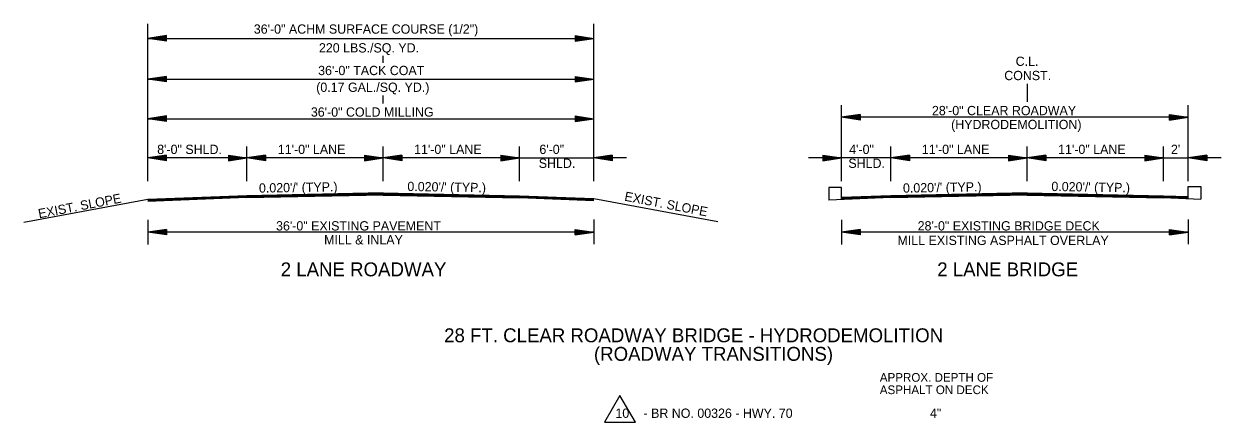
# Model space of a CAD drawing. Extents: x 549600 to 1930787, y -1955432 to 596640.
# Drawn here: x 551046 to 552013, y -1948810 to -1948488 of the extents above; entities that cross this region are included whole.
import ezdxf

# ---------------------------------------------------------------- set-up
doc = ezdxf.new("R2010")
doc.units = 0
for name, color, linetype in [('R_Border', 7, 'Continuous'), ('R_Border Notes', 7, 'Continuous'), ('S_AREA_CALC', 7, 'Continuous')]:
    doc.layers.add(name, color=color, linetype=linetype)

msp = doc.modelspace()

# ---------------------------------------------------------------- linework, layer by layer
at = {"layer": 'R_Border'}
for p, q in [((551856.56, -1948536.2), (551856.56, -1948550.7)), ((551696.39, -1948619.94), (551696.39, -1948630.06)), ((551706.56, -1948619.94), (551696.39, -1948619.94)), ((551706.56, -1948629.35), (551706.56, -1948619.94)), ((551986.56, -1948628.55), (551986.56, -1948619.14)), ((551986.56, -1948619.14), (551996.73, -1948619.14)), ((551996.73, -1948619.14), (551996.73, -1948629.26)), ((551515.35, -1948809.5), (551540.15, -1948809.5))]:
    msp.add_line(p, q, dxfattribs=at)
msp.add_lwpolyline([(551540.15, -1948809.5), (551527.75, -1948788.03), (551515.35, -1948809.5)], dxfattribs=at)
at = {"layer": 'S_AREA_CALC'}
for p, q in [((551146.56, -1948614.8), (551146.56, -1948487.77)), ((551506.56, -1948614.8), (551506.56, -1948487.77)), ((551161.56, -1948497.19), (551146.56, -1948499.44)), ((551146.56, -1948499.44), (551506.56, -1948499.44)), ((551161.56, -1948501.69), (551146.56, -1948499.44)), ((551161.56, -1948497.56), (551149.06, -1948499.44)), ((551161.56, -1948501.31), (551149.06, -1948499.44)), ((551161.56, -1948497.95), (551151.64, -1948499.44)), ((551161.56, -1948500.93), (551151.64, -1948499.44)), ((551161.56, -1948498.32), (551154.14, -1948499.44)), ((551161.56, -1948500.56), (551154.14, -1948499.44)), ((551161.56, -1948498.7), (551156.68, -1948499.44)), ((551161.56, -1948500.17), (551156.68, -1948499.44)), ((551161.56, -1948499.09), (551159.19, -1948499.44)), ((551161.56, -1948499.79), (551159.19, -1948499.44)), ((551161.56, -1948501.69), (551161.56, -1948497.19)), ((551491.56, -1948497.19), (551506.56, -1948499.44)), ((551491.56, -1948497.19), (551491.56, -1948501.69)), ((551491.56, -1948497.56), (551504.05, -1948499.44)), ((551491.56, -1948497.95), (551501.47, -1948499.44)), ((551491.56, -1948498.32), (551498.98, -1948499.44)), ((551491.56, -1948498.71), (551496.43, -1948499.44)), ((551491.56, -1948499.09), (551493.93, -1948499.44)), ((551491.56, -1948501.69), (551506.56, -1948499.44)), ((551491.56, -1948500.17), (551496.43, -1948499.44)), ((551491.56, -1948500.93), (551501.47, -1948499.44)), ((551491.56, -1948501.31), (551504.05, -1948499.44)), ((551491.56, -1948500.56), (551498.98, -1948499.44)), ((551491.56, -1948499.79), (551493.93, -1948499.44)), ((551336.56, -1948519.18), (551336.56, -1948513.65)), ((551161.56, -1948530.15), (551146.56, -1948532.4)), ((551146.56, -1948532.4), (551506.56, -1948532.4)), ((551161.56, -1948534.65), (551146.56, -1948532.4)), ((551161.56, -1948530.53), (551149.06, -1948532.4)), ((551161.56, -1948534.28), (551149.06, -1948532.4)), ((551161.56, -1948530.91), (551151.64, -1948532.4)), ((551161.56, -1948533.9), (551151.64, -1948532.4)), ((551161.56, -1948531.29), (551154.14, -1948532.4)), ((551161.56, -1948533.52), (551154.14, -1948532.4)), ((551161.56, -1948531.67), (551156.68, -1948532.4)), ((551161.56, -1948533.13), (551156.68, -1948532.4)), ((551161.56, -1948532.05), (551159.19, -1948532.4)), ((551161.56, -1948532.76), (551159.19, -1948532.4)), ((551161.56, -1948534.65), (551161.56, -1948530.15)), ((551491.56, -1948530.15), (551506.56, -1948532.4)), ((551491.56, -1948530.15), (551491.56, -1948534.65)), ((551491.56, -1948530.53), (551504.05, -1948532.4)), ((551491.56, -1948530.91), (551501.47, -1948532.4)), ((551491.56, -1948531.29), (551498.98, -1948532.4)), ((551491.56, -1948531.68), (551496.43, -1948532.4)), ((551491.56, -1948532.05), (551493.93, -1948532.4)), ((551491.56, -1948534.65), (551506.56, -1948532.4)), ((551491.56, -1948533.14), (551496.43, -1948532.4)), ((551491.56, -1948533.9), (551501.47, -1948532.4)), ((551491.56, -1948534.28), (551504.05, -1948532.4)), ((551491.56, -1948533.52), (551498.98, -1948532.4)), ((551491.56, -1948532.76), (551493.93, -1948532.4)), ((551336.56, -1948552.15), (551336.56, -1948545.73)), ((551706.56, -1948614.8), (551706.56, -1948553.31)), ((551986.56, -1948614.8), (551986.56, -1948553.31)), ((551161.56, -1948562.13), (551146.56, -1948564.38)), ((551146.56, -1948564.38), (551506.56, -1948564.38)), ((551161.56, -1948566.63), (551146.56, -1948564.38)), ((551161.56, -1948562.5), (551149.06, -1948564.38)), ((551161.56, -1948566.25), (551149.06, -1948564.38)), ((551161.56, -1948562.89), (551151.64, -1948564.38)), ((551161.56, -1948565.87), (551151.64, -1948564.38)), ((551161.56, -1948563.26), (551154.14, -1948564.38)), ((551161.56, -1948565.5), (551154.14, -1948564.38)), ((551161.56, -1948563.64), (551156.68, -1948564.38)), ((551161.56, -1948565.11), (551156.68, -1948564.38)), ((551161.56, -1948564.03), (551159.19, -1948564.38)), ((551161.56, -1948564.73), (551159.19, -1948564.38)), ((551161.56, -1948566.63), (551161.56, -1948562.13)), ((551491.56, -1948562.13), (551506.56, -1948564.38)), ((551491.56, -1948562.13), (551491.56, -1948566.63)), ((551491.56, -1948562.5), (551504.05, -1948564.38)), ((551491.56, -1948562.89), (551501.47, -1948564.38)), ((551491.56, -1948563.26), (551498.98, -1948564.38)), ((551491.56, -1948563.65), (551496.43, -1948564.38)), ((551491.56, -1948564.03), (551493.93, -1948564.38)), ((551491.56, -1948566.63), (551506.56, -1948564.38)), ((551491.56, -1948565.11), (551496.43, -1948564.38)), ((551491.56, -1948565.87), (551501.47, -1948564.38)), ((551491.56, -1948566.25), (551504.05, -1948564.38)), ((551491.56, -1948565.5), (551498.98, -1948564.38)), ((551491.56, -1948564.73), (551493.93, -1948564.38)), ((551721.56, -1948560.95), (551706.56, -1948563.2)), ((551986.56, -1948563.2), (551706.56, -1948563.2)), ((551721.56, -1948565.45), (551706.56, -1948563.2)), ((551721.56, -1948561.33), (551709.06, -1948563.2)), ((551721.56, -1948565.08), (551709.06, -1948563.2)), ((551721.56, -1948561.71), (551711.64, -1948563.2)), ((551721.56, -1948564.7), (551711.64, -1948563.2)), ((551721.56, -1948562.09), (551714.14, -1948563.2)), ((551721.56, -1948564.32), (551714.14, -1948563.2)), ((551721.56, -1948562.48), (551716.68, -1948563.2)), ((551721.56, -1948563.94), (551716.68, -1948563.2)), ((551721.56, -1948562.85), (551719.19, -1948563.2)), ((551721.56, -1948563.56), (551719.19, -1948563.2)), ((551721.56, -1948560.95), (551721.56, -1948565.45)), ((551971.56, -1948560.95), (551986.56, -1948563.2)), ((551971.56, -1948565.45), (551971.56, -1948560.95)), ((551971.56, -1948561.33), (551984.05, -1948563.2)), ((551971.56, -1948561.71), (551981.47, -1948563.2)), ((551971.56, -1948562.09), (551978.98, -1948563.2)), ((551971.56, -1948562.47), (551976.43, -1948563.2)), ((551971.56, -1948562.85), (551973.93, -1948563.2)), ((551971.56, -1948565.45), (551986.56, -1948563.2)), ((551971.56, -1948563.93), (551976.43, -1948563.2)), ((551971.56, -1948564.7), (551981.47, -1948563.2)), ((551971.56, -1948565.08), (551984.05, -1948563.2)), ((551971.56, -1948564.32), (551978.98, -1948563.2)), ((551971.56, -1948563.56), (551973.93, -1948563.2)), ((551226.56, -1948614.8), (551226.56, -1948586.85)), ((551336.56, -1948614.8), (551336.56, -1948586.85)), ((551446.56, -1948614.8), (551446.56, -1948586.85)), ((551746.56, -1948614.8), (551746.56, -1948586.85)), ((551856.56, -1948614.8), (551856.56, -1948586.85)), ((551966.56, -1948614.8), (551966.56, -1948586.85)), ((551161.56, -1948593.79), (551146.56, -1948596.04)), ((551226.56, -1948596.04), (551146.56, -1948596.04)), ((551161.56, -1948598.29), (551146.56, -1948596.04)), ((551161.56, -1948594.16), (551149.06, -1948596.04)), ((551161.56, -1948597.91), (551149.06, -1948596.04)), ((551161.56, -1948594.55), (551151.64, -1948596.04)), ((551161.56, -1948597.53), (551151.64, -1948596.04)), ((551161.56, -1948594.92), (551154.14, -1948596.04)), ((551161.56, -1948597.16), (551154.14, -1948596.04)), ((551161.56, -1948595.3), (551156.68, -1948596.04)), ((551161.56, -1948596.77), (551156.68, -1948596.04)), ((551161.56, -1948595.69), (551159.19, -1948596.04)), ((551161.56, -1948596.39), (551159.19, -1948596.04)), ((551161.56, -1948598.29), (551161.56, -1948593.79)), ((551211.56, -1948593.79), (551226.56, -1948596.04)), ((551211.56, -1948593.79), (551211.56, -1948598.29)), ((551211.56, -1948594.16), (551224.05, -1948596.04)), ((551211.56, -1948594.55), (551221.47, -1948596.04)), ((551211.56, -1948594.92), (551218.98, -1948596.04)), ((551211.56, -1948595.31), (551216.43, -1948596.04)), ((551211.56, -1948595.69), (551213.93, -1948596.04)), ((551211.56, -1948598.29), (551226.56, -1948596.04)), ((551211.56, -1948596.77), (551216.43, -1948596.04)), ((551211.56, -1948597.53), (551221.47, -1948596.04)), ((551211.56, -1948597.91), (551224.05, -1948596.04)), ((551211.56, -1948597.16), (551218.98, -1948596.04)), ((551211.56, -1948596.39), (551213.93, -1948596.04)), ((551241.56, -1948593.79), (551226.56, -1948596.04)), ((551336.56, -1948596.04), (551226.56, -1948596.04)), ((551241.56, -1948598.29), (551226.56, -1948596.04)), ((551241.56, -1948594.16), (551229.06, -1948596.04)), ((551241.56, -1948597.91), (551229.06, -1948596.04)), ((551241.56, -1948594.55), (551231.64, -1948596.04)), ((551241.56, -1948597.53), (551231.64, -1948596.04)), ((551241.56, -1948594.92), (551234.14, -1948596.04)), ((551241.56, -1948597.16), (551234.14, -1948596.04)), ((551241.56, -1948595.31), (551236.68, -1948596.04)), ((551241.56, -1948596.77), (551236.68, -1948596.04)), ((551241.56, -1948595.69), (551239.19, -1948596.04)), ((551241.56, -1948596.39), (551239.19, -1948596.04)), ((551241.56, -1948593.79), (551241.56, -1948598.29)), ((551321.56, -1948593.79), (551336.56, -1948596.04)), ((551321.56, -1948593.79), (551321.56, -1948598.29)), ((551321.56, -1948594.16), (551334.05, -1948596.04)), ((551321.56, -1948594.55), (551331.47, -1948596.04)), ((551321.56, -1948594.92), (551328.98, -1948596.04)), ((551321.56, -1948595.31), (551326.43, -1948596.04)), ((551321.56, -1948595.69), (551323.93, -1948596.04)), ((551321.56, -1948598.29), (551336.56, -1948596.04)), ((551321.56, -1948596.77), (551326.43, -1948596.04)), ((551321.56, -1948597.53), (551331.47, -1948596.04)), ((551321.56, -1948597.91), (551334.05, -1948596.04)), ((551321.56, -1948597.16), (551328.98, -1948596.04)), ((551321.56, -1948596.39), (551323.93, -1948596.04)), ((551351.56, -1948593.79), (551336.56, -1948596.04)), ((551446.56, -1948596.04), (551336.56, -1948596.04)), ((551351.56, -1948598.29), (551336.56, -1948596.04)), ((551351.56, -1948594.16), (551339.06, -1948596.04)), ((551351.56, -1948597.91), (551339.06, -1948596.04)), ((551351.56, -1948594.55), (551341.64, -1948596.04)), ((551351.56, -1948597.53), (551341.64, -1948596.04)), ((551351.56, -1948594.92), (551344.14, -1948596.04)), ((551351.56, -1948597.16), (551344.14, -1948596.04)), ((551351.56, -1948595.31), (551346.68, -1948596.04)), ((551351.56, -1948596.77), (551346.68, -1948596.04)), ((551351.56, -1948595.69), (551349.19, -1948596.04)), ((551351.56, -1948596.39), (551349.19, -1948596.04)), ((551351.56, -1948593.79), (551351.56, -1948598.29)), ((551431.56, -1948593.79), (551446.56, -1948596.04)), ((551431.56, -1948593.79), (551431.56, -1948598.29)), ((551431.56, -1948594.16), (551444.05, -1948596.04)), ((551431.56, -1948594.55), (551441.47, -1948596.04)), ((551431.56, -1948594.92), (551438.98, -1948596.04)), ((551431.56, -1948595.31), (551436.43, -1948596.04)), ((551431.56, -1948595.69), (551433.93, -1948596.04)), ((551431.56, -1948598.29), (551446.56, -1948596.04)), ((551431.56, -1948596.77), (551436.43, -1948596.04)), ((551431.56, -1948597.53), (551441.47, -1948596.04)), ((551431.56, -1948597.91), (551444.05, -1948596.04)), ((551431.56, -1948597.16), (551438.98, -1948596.04)), ((551431.56, -1948596.39), (551433.93, -1948596.04)), ((551446.56, -1948596.04), (551506.56, -1948596.04)), ((551521.56, -1948593.79), (551506.56, -1948596.04)), ((551521.56, -1948598.29), (551506.56, -1948596.04)), ((551533.08, -1948596.04), (551506.56, -1948596.04)), ((551521.56, -1948594.16), (551509.06, -1948596.04)), ((551521.56, -1948597.91), (551509.06, -1948596.04)), ((551521.56, -1948594.55), (551511.64, -1948596.04)), ((551521.56, -1948597.53), (551511.64, -1948596.04)), ((551521.56, -1948594.92), (551514.14, -1948596.04)), ((551521.56, -1948597.16), (551514.14, -1948596.04)), ((551521.56, -1948595.31), (551516.68, -1948596.04)), ((551521.56, -1948596.77), (551516.68, -1948596.04)), ((551521.56, -1948595.69), (551519.19, -1948596.04)), ((551521.56, -1948596.39), (551519.19, -1948596.04)), ((551521.56, -1948593.79), (551521.56, -1948598.29)), ((551706.56, -1948596.04), (551680.04, -1948596.04)), ((551691.56, -1948593.79), (551706.56, -1948596.04)), ((551691.56, -1948593.79), (551691.56, -1948598.29)), ((551691.56, -1948594.16), (551704.05, -1948596.04)), ((551691.56, -1948594.55), (551701.47, -1948596.04)), ((551691.56, -1948594.92), (551698.98, -1948596.04)), ((551691.56, -1948595.31), (551696.43, -1948596.04)), ((551691.56, -1948595.69), (551693.93, -1948596.04)), ((551691.56, -1948598.29), (551706.56, -1948596.04)), ((551691.56, -1948596.77), (551696.43, -1948596.04)), ((551691.56, -1948597.53), (551701.47, -1948596.04)), ((551691.56, -1948597.91), (551704.05, -1948596.04)), ((551691.56, -1948597.16), (551698.98, -1948596.04)), ((551691.56, -1948596.39), (551693.93, -1948596.04)), ((551746.56, -1948596.04), (551706.56, -1948596.04)), ((551761.56, -1948593.79), (551746.56, -1948596.04)), ((551856.56, -1948596.04), (551746.56, -1948596.04)), ((551761.56, -1948598.29), (551746.56, -1948596.04)), ((551761.56, -1948594.16), (551749.06, -1948596.04)), ((551761.56, -1948597.91), (551749.06, -1948596.04)), ((551761.56, -1948594.55), (551751.64, -1948596.04)), ((551761.56, -1948597.53), (551751.64, -1948596.04)), ((551761.56, -1948594.92), (551754.14, -1948596.04)), ((551761.56, -1948597.16), (551754.14, -1948596.04)), ((551761.56, -1948595.31), (551756.68, -1948596.04)), ((551761.56, -1948596.77), (551756.68, -1948596.04)), ((551761.56, -1948595.69), (551759.19, -1948596.04)), ((551761.56, -1948596.39), (551759.19, -1948596.04)), ((551761.56, -1948593.79), (551761.56, -1948598.29)), ((551841.56, -1948593.79), (551856.56, -1948596.04)), ((551841.56, -1948593.79), (551841.56, -1948598.29)), ((551841.56, -1948594.16), (551854.05, -1948596.04)), ((551841.56, -1948594.55), (551851.47, -1948596.04)), ((551841.56, -1948594.92), (551848.98, -1948596.04)), ((551841.56, -1948595.31), (551846.43, -1948596.04)), ((551841.56, -1948595.69), (551843.93, -1948596.04)), ((551841.56, -1948598.29), (551856.56, -1948596.04)), ((551841.56, -1948596.77), (551846.43, -1948596.04)), ((551841.56, -1948597.53), (551851.47, -1948596.04)), ((551841.56, -1948597.91), (551854.05, -1948596.04)), ((551841.56, -1948597.16), (551848.98, -1948596.04)), ((551841.56, -1948596.39), (551843.93, -1948596.04)), ((551871.56, -1948593.79), (551856.56, -1948596.04)), ((551966.56, -1948596.04), (551856.56, -1948596.04)), ((551871.56, -1948598.29), (551856.56, -1948596.04)), ((551871.56, -1948594.16), (551859.06, -1948596.04)), ((551871.56, -1948597.91), (551859.06, -1948596.04)), ((551871.56, -1948594.55), (551861.64, -1948596.04)), ((551871.56, -1948597.53), (551861.64, -1948596.04)), ((551871.56, -1948594.92), (551864.14, -1948596.04)), ((551871.56, -1948597.16), (551864.14, -1948596.04)), ((551871.56, -1948595.31), (551866.68, -1948596.04)), ((551871.56, -1948596.77), (551866.68, -1948596.04)), ((551871.56, -1948595.69), (551869.19, -1948596.04)), ((551871.56, -1948596.39), (551869.19, -1948596.04)), ((551871.56, -1948593.79), (551871.56, -1948598.29)), ((551951.56, -1948593.79), (551966.56, -1948596.04)), ((551951.56, -1948593.79), (551951.56, -1948598.29)), ((551951.56, -1948594.16), (551964.05, -1948596.04)), ((551951.56, -1948594.55), (551961.47, -1948596.04)), ((551951.56, -1948594.92), (551958.98, -1948596.04)), ((551951.56, -1948595.31), (551956.43, -1948596.04)), ((551951.56, -1948595.69), (551953.93, -1948596.04)), ((551951.56, -1948598.29), (551966.56, -1948596.04)), ((551951.56, -1948596.77), (551956.43, -1948596.04)), ((551951.56, -1948597.53), (551961.47, -1948596.04)), ((551951.56, -1948597.91), (551964.05, -1948596.04)), ((551951.56, -1948597.16), (551958.98, -1948596.04)), ((551951.56, -1948596.39), (551953.93, -1948596.04)), ((551966.56, -1948596.04), (551986.56, -1948596.04)), ((552001.56, -1948593.79), (551986.56, -1948596.04)), ((552001.56, -1948598.29), (551986.56, -1948596.04)), ((552013.08, -1948596.04), (551986.56, -1948596.04)), ((552001.56, -1948594.16), (551989.06, -1948596.04)), ((552001.56, -1948597.91), (551989.06, -1948596.04)), ((552001.56, -1948594.55), (551991.64, -1948596.04)), ((552001.56, -1948597.53), (551991.64, -1948596.04)), ((552001.56, -1948594.92), (551994.14, -1948596.04)), ((552001.56, -1948597.16), (551994.14, -1948596.04)), ((552001.56, -1948595.31), (551996.68, -1948596.04)), ((552001.56, -1948596.77), (551996.68, -1948596.04)), ((552001.56, -1948595.69), (551999.19, -1948596.04)), ((552001.56, -1948596.39), (551999.19, -1948596.04)), ((552001.56, -1948593.79), (552001.56, -1948598.29)), ((551146.56, -1948629.75), (551046.49, -1948648.12)), ((551226.56, -1948626.55), (551146.56, -1948629.75)), ((551226.56, -1948626.85), (551146.56, -1948630.05)), ((551226.56, -1948627.15), (551146.56, -1948630.35)), ((551226.56, -1948627.45), (551146.56, -1948630.65)), ((551226.56, -1948627.75), (551146.56, -1948630.95)), ((551226.56, -1948628.05), (551146.56, -1948631.25)), ((551336.56, -1948624.35), (551226.56, -1948626.55)), ((551336.56, -1948624.65), (551226.56, -1948626.85)), ((551336.56, -1948624.95), (551226.56, -1948627.15)), ((551336.56, -1948625.25), (551226.56, -1948627.45)), ((551336.56, -1948625.55), (551226.56, -1948627.75)), ((551336.56, -1948625.85), (551226.56, -1948628.05)), ((551336.56, -1948626.02), (551226.56, -1948628.22)), ((551336.56, -1948624.35), (551446.56, -1948626.55)), ((551336.56, -1948624.65), (551446.56, -1948626.85)), ((551336.56, -1948624.95), (551446.56, -1948627.15)), ((551336.56, -1948625.25), (551446.56, -1948627.45)), ((551336.56, -1948625.55), (551446.56, -1948627.75)), ((551336.56, -1948625.85), (551446.56, -1948628.05)), ((551336.56, -1948626.02), (551446.56, -1948628.22)), ((551446.56, -1948626.55), (551506.56, -1948628.95)), ((551446.56, -1948626.85), (551506.56, -1948629.25)), ((551446.56, -1948627.15), (551506.56, -1948629.55)), ((551446.56, -1948627.45), (551506.56, -1948629.85)), ((551446.56, -1948627.75), (551506.56, -1948630.15)), ((551446.56, -1948628.05), (551506.56, -1948630.45)), ((551506.56, -1948628.95), (551606.63, -1948647.32)), ((551746.56, -1948628.05), (551696.39, -1948630.06)), ((551746.56, -1948626.55), (551706.56, -1948628.15)), ((551746.56, -1948626.85), (551706.56, -1948628.45)), ((551746.56, -1948627.15), (551706.56, -1948628.75)), ((551746.56, -1948627.45), (551706.56, -1948629.05)), ((551746.56, -1948627.75), (551706.56, -1948629.35)), ((551856.56, -1948624.35), (551746.56, -1948626.55)), ((551856.56, -1948624.65), (551746.56, -1948626.85)), ((551856.56, -1948624.95), (551746.56, -1948627.15)), ((551856.56, -1948625.25), (551746.56, -1948627.45)), ((551856.56, -1948625.55), (551746.56, -1948627.75)), ((551856.56, -1948625.85), (551746.56, -1948628.05)), ((551856.56, -1948626.02), (551746.56, -1948628.22)), ((551856.56, -1948624.35), (551966.56, -1948626.55)), ((551856.56, -1948624.65), (551966.56, -1948626.85)), ((551856.56, -1948624.95), (551966.56, -1948627.15)), ((551856.56, -1948625.25), (551966.56, -1948627.45)), ((551856.56, -1948625.55), (551966.56, -1948627.75)), ((551856.56, -1948625.85), (551966.56, -1948628.05)), ((551856.56, -1948626.02), (551966.56, -1948628.22)), ((551966.56, -1948626.55), (551986.56, -1948627.35)), ((551966.56, -1948626.85), (551986.56, -1948627.65)), ((551966.56, -1948627.15), (551986.56, -1948627.95)), ((551966.56, -1948627.45), (551986.56, -1948628.25)), ((551966.56, -1948627.75), (551986.56, -1948628.55)), ((551966.56, -1948628.05), (551996.73, -1948629.26)), ((551146.56, -1948646.01), (551146.56, -1948666.01)), ((551506.56, -1948645.76), (551506.56, -1948665.76)), ((551706.56, -1948646.01), (551706.56, -1948666.01)), ((551986.56, -1948645.76), (551986.56, -1948665.76)), ((551161.56, -1948653.76), (551146.56, -1948656.01)), ((551161.56, -1948658.26), (551146.56, -1948656.01)), ((551506.56, -1948656.01), (551146.56, -1948656.01)), ((551161.56, -1948654.13), (551149.06, -1948656.01)), ((551161.56, -1948657.88), (551149.06, -1948656.01)), ((551161.56, -1948654.51), (551151.64, -1948656.01)), ((551161.56, -1948657.5), (551151.64, -1948656.01)), ((551161.56, -1948654.89), (551154.14, -1948656.01)), ((551161.56, -1948657.12), (551154.14, -1948656.01)), ((551161.56, -1948655.28), (551156.68, -1948656.01)), ((551161.56, -1948656.74), (551156.68, -1948656.01)), ((551161.56, -1948655.65), (551159.19, -1948656.01)), ((551161.56, -1948656.36), (551159.19, -1948656.01)), ((551161.56, -1948653.76), (551161.56, -1948658.26)), ((551491.56, -1948653.76), (551506.56, -1948656.01)), ((551491.56, -1948658.26), (551491.56, -1948653.76)), ((551491.56, -1948654.13), (551504.05, -1948656.01)), ((551491.56, -1948654.51), (551501.47, -1948656.01)), ((551491.56, -1948654.89), (551498.98, -1948656.01)), ((551491.56, -1948655.27), (551496.43, -1948656.01)), ((551491.56, -1948655.65), (551493.93, -1948656.01)), ((551491.56, -1948658.26), (551506.56, -1948656.01)), ((551491.56, -1948656.73), (551496.43, -1948656.01)), ((551491.56, -1948657.5), (551501.47, -1948656.01)), ((551491.56, -1948657.88), (551504.05, -1948656.01)), ((551491.56, -1948657.12), (551498.98, -1948656.01)), ((551491.56, -1948656.36), (551493.93, -1948656.01)), ((551721.56, -1948653.76), (551706.56, -1948656.01)), ((551721.56, -1948658.26), (551706.56, -1948656.01)), ((551986.56, -1948656.01), (551706.56, -1948656.01)), ((551721.56, -1948654.13), (551709.06, -1948656.01)), ((551721.56, -1948657.88), (551709.06, -1948656.01)), ((551721.56, -1948654.51), (551711.64, -1948656.01)), ((551721.56, -1948657.5), (551711.64, -1948656.01)), ((551721.56, -1948654.89), (551714.14, -1948656.01)), ((551721.56, -1948657.12), (551714.14, -1948656.01)), ((551721.56, -1948655.28), (551716.68, -1948656.01)), ((551721.56, -1948656.74), (551716.68, -1948656.01)), ((551721.56, -1948655.65), (551719.19, -1948656.01)), ((551721.56, -1948656.36), (551719.19, -1948656.01)), ((551721.56, -1948653.76), (551721.56, -1948658.26)), ((551971.56, -1948653.76), (551986.56, -1948656.01)), ((551971.56, -1948658.26), (551971.56, -1948653.76)), ((551971.56, -1948654.13), (551984.05, -1948656.01)), ((551971.56, -1948654.51), (551981.47, -1948656.01)), ((551971.56, -1948654.89), (551978.98, -1948656.01)), ((551971.56, -1948655.27), (551976.43, -1948656.01)), ((551971.56, -1948655.65), (551973.93, -1948656.01)), ((551971.56, -1948658.26), (551986.56, -1948656.01)), ((551971.56, -1948656.73), (551976.43, -1948656.01)), ((551971.56, -1948657.5), (551981.47, -1948656.01)), ((551971.56, -1948657.88), (551984.05, -1948656.01)), ((551971.56, -1948657.12), (551978.98, -1948656.01)), ((551971.56, -1948656.36), (551973.93, -1948656.01))]:
    msp.add_line(p, q, dxfattribs=at)

# ---------------------------------------------------------------- texts
at = {"layer": 'R_Border'}
for s, height, p in [('C.L.', 7.5, (551847.23, -1948521.7)), ('CONST.', 7.5, (551838.01, -1948533.2)), ('28 FT. CLEAR ROADWAY BRIDGE - HYDRODEMOLITION', 11.25, (551385.77, -1948745.01)), ('(ROADWAY TRANSITIONS)', 11.25, (551506.73, -1948760.01)), ('10', 7.5, (551524.06, -1948806.09)), ('- BR NO. 00326 - HWY. 70', 7.5, (551546.75, -1948806.09)), ('4"', 7.5, (551778.06, -1948806.09))]:
    msp.add_text(s, height=height, dxfattribs=at).set_placement(p)
at = {"layer": 'R_Border Notes'}
for s, p in [('APPROX. DEPTH OF', (551737.53, -1948776.91)), ('ASPHALT ON DECK', (551737.53, -1948786.91))]:
    msp.add_text(s, height=7, dxfattribs=at).set_placement(p)
at = {"layer": 'S_AREA_CALC'}
for s, height, p in [('36\'-0" ACHM SURFACE COURSE (1/2")', 7.5, (551232.09, -1948495.67)), ('220 LBS./SQ. YD. ', 7.5, (551284.68, -1948510.85)), ('36\'-0" TACK COAT', 7.5, (551284.03, -1948529.14)), ('(0.17 GAL./SQ. YD.)', 7.5, (551282.47, -1948542.68)), ('28\'-0" CLEAR ROADWAY', 7.5, (551779.65, -1948561.53)), ('36\'-0" COLD MILLING ', 7.5, (551278.18, -1948562.71)), ('(HYDRODEMOLITION)', 7.5, (551795.12, -1948572.78)), ('8\'-0" SHLD.', 7.5, (551154.08, -1948592.87)), ('11\'-0" LANE', 7.5, (551251.5, -1948592.87)), ('11\'-0" LANE', 7.5, (551361.5, -1948592.87)), ('6\'-0"', 7.5, (551462.65, -1948592.87)), ('4\'-0"', 7.5, (551712.83, -1948592.87)), ('11\'-0" LANE', 7.5, (551771.5, -1948592.87)), ('11\'-0" LANE', 7.5, (551881.5, -1948592.87)), ("2'", 7.5, (551972.6, -1948592.87)), ('SHLD.', 7.5, (551462.15, -1948604.12)), ('SHLD.', 7.5, (551712.15, -1948604.12)), ('36\'-0" EXISTING PAVEMENT', 7.5, (551250.05, -1948654.68)), ('28\'-0" EXISTING BRIDGE DECK', 7.5, (551768.11, -1948654.68)), ('MILL & INLAY', 7.5, (551288.88, -1948665.96)), ('MILL EXISTING ASPHALT OVERLAY', 7.5, (551751.83, -1948666.4)), ('2 LANE ROADWAY', 11.25, (551253.83, -1948691.72)), ('2 LANE BRIDGE', 11.25, (551783.93, -1948691.72))]:
    msp.add_text(s, height=height, dxfattribs=at).set_placement(p)
for s, rotation, p in [("0.020'/' (TYP.)", 0.97192, (551236.3, -1948624.14)), ("0.020'/' (TYP.)", 359.02808, (551356.04, -1948622.77)), ("0.020'/' (TYP.)", 0.97192, (551756.3, -1948624.14)), ("0.020'/' (TYP.)", 359.02808, (551876.04, -1948622.77)), ('EXIST. SLOPE', 10.88286, (551058.77, -1948644.91)), ('EXIST. SLOPE', 349.11714, (551530.94, -1948630.54))]:
    msp.add_text(s, height=7.5, rotation=rotation, dxfattribs=at).set_placement(p)

doc.saveas('drawing.dxf')
